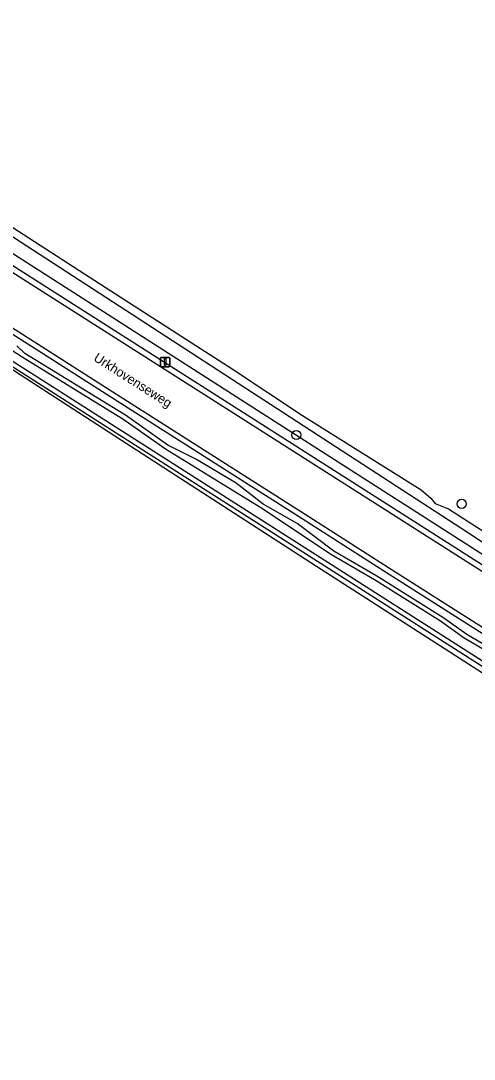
# Model space of a CAD drawing. Extents: x 164494 to 166241, y 382475 to 384494.
# Drawn here: x 165274.1 to 165322.7, y 382859.3 to 382970.6 of the extents above; entities that cross this region are included whole.
import ezdxf

# ---------------------------------------------------------------- set-up
doc = ezdxf.new("R2010")
doc.units = 0
for name, color, linetype in [('IMGEO_Berm_halfverhard', 7, 'Continuous'), ('IMGEO_Boom', 7, 'Continuous'), ('IMGEO_Grasland_agrarisch', 7, 'Continuous'), ('IMGEO_Groenvoorziening', 7, 'Continuous'), ('IMGEO_Hek', 7, 'Continuous'), ('IMGEO_Loofbos', 7, 'Continuous'), ('IMGEO_Openbare_ruimte_label', 7, 'Continuous'), ('IMGEO_Rijbaan_lokaal_gesloten', 7, 'Continuous'), ('IMGEO_Verkeersbordpaal', 7, 'Continuous'), ('IMGEO_Waterloop', 7, 'Continuous')]:
    doc.layers.add(name, color=color, linetype=linetype)

msp = doc.modelspace()

# ---------------------------------------------------------------- linework, layer by layer
at = {"layer": 'IMGEO_Berm_halfverhard'}
for points in [[(165252.94, 382956.51), (165253.27, 382957.02), (165336.85, 382903.81), (165336.73, 382903.62), (165352.54, 382893.38)], [(165351.59, 382887), (165346.66, 382890.15), (165339.82, 382894.53), (165330.45, 382900.53), (165322.57, 382905.52), (165313.17, 382911.49), (165304.23, 382917.2), (165295.7, 382922.63), (165290.59, 382925.86), (165282.82, 382930.8), (165276, 382935.15), (165269.08, 382939.56), (165261.99, 382944.04), (165250.07, 382951.57), (165250.4, 382952.08)]]:
    msp.add_lwpolyline(points, dxfattribs=at)
at = {"layer": 'IMGEO_Boom'}
for centre in [(165303.61, 382926.18), (165321.33, 382918.8)]:
    msp.add_circle(centre, 0.489, dxfattribs=at)
at = {"layer": 'IMGEO_Grasland_agrarisch'}
msp.add_lwpolyline([(165240.44, 382969.54), (165240.65, 382969.41), (165269.04, 382951.11), (165283.23, 382941.96), (165296.82, 382933.2), (165304.27, 382928.28), (165316.97, 382920.29), (165318.03, 382919.42), (165318.5, 382918.84), (165319.92, 382918.27), (165332.19, 382910.35), (165332.59, 382910.4), (165333.72, 382909.38), (165356.3, 382895.09), (165364.07, 382889.81), (165370.04, 382885.4), (165371.91, 382884.35), (165372.87, 382883.34)], dxfattribs=at)
at = {"layer": 'IMGEO_Groenvoorziening'}
msp.add_lwpolyline([(165363.51, 382875.32), (165364.7, 382877.15), (165360.69, 382879.91), (165359.12, 382880.68), (165347.27, 382888.35), (165336.18, 382895.87), (165332.89, 382897.74), (165327.6, 382901.45), (165321.86, 382904.8), (165319.31, 382906.62), (165312.22, 382911.06), (165307.64, 382913.72), (165303.7, 382916.7), (165300.05, 382918.77), (165297.15, 382921.02), (165292.89, 382923.56), (165289.84, 382925.08), (165285.28, 382928.29), (165284.46, 382928.79), (165274.52, 382934.91), (165273.65, 382935.73)], dxfattribs=at)
at = {"layer": 'IMGEO_Hek'}
for points in [[(165284.75, 382925.67), (165260.58, 382941.3), (165247.02, 382950.24)], [(165339.77, 382859.26), (165360.03, 382877.2), (165305.75, 382912.08), (165284.75, 382925.67)]]:
    msp.add_lwpolyline(points, dxfattribs=at)
at = {"layer": 'IMGEO_Loofbos'}
for points in [[(165339.77, 382859.26), (165360.03, 382877.2), (165305.75, 382912.08), (165284.75, 382925.67), (165260.58, 382941.3), (165247.02, 382950.24)], [(165247.02, 382950.24), (165260.73, 382941.64), (165271.58, 382934.54), (165284.7, 382926.17), (165326.65, 382899.4), (165363.51, 382875.32)]]:
    msp.add_lwpolyline(points, dxfattribs=at)
at = {"layer": 'IMGEO_Rijbaan_lokaal_gesloten'}
for points in [[(165252.94, 382956.51), (165336.52, 382903.3), (165343.27, 382899)], [(165250.4, 382952.08), (165262.31, 382944.54), (165269.4, 382940.07), (165276.32, 382935.66), (165283.14, 382931.31), (165290.91, 382926.37), (165296.02, 382923.13), (165304.55, 382917.7), (165313.49, 382911.99), (165322.89, 382906.02), (165330.77, 382901.04), (165340.15, 382895.04), (165346.98, 382890.66), (165351.91, 382887.51)]]:
    msp.add_lwpolyline(points, dxfattribs=at)
at = {"layer": 'IMGEO_Verkeersbordpaal'}
for p, q in [((165289.06, 382933.6), (165289.06, 382934.4)), ((165289.06, 382934.4), (165289.06, 382933.6)), ((165289.16, 382934.5), (165289.95, 382934.5)), ((165289.95, 382934.5), (165289.16, 382934.5)), ((165290.05, 382934.4), (165290.05, 382933.6)), ((165290.05, 382933.6), (165290.05, 382934.4)), ((165289.95, 382933.5), (165289.16, 382933.5)), ((165289.16, 382933.5), (165289.95, 382933.5))]:
    msp.add_line(p, q, dxfattribs=at)
msp.add_lwpolyline([(165289.48, 382934.38), (165289.63, 382934.38), (165289.63, 382933.63), (165289.48, 382933.63), (165289.48, 382934.38)], dxfattribs=at)
for centre, start, end in [((165289.16, 382934.4), 90, 180), ((165289.16, 382934.4), 90, 180), ((165289.95, 382934.4), 0, 90), ((165289.95, 382934.4), 360, 90), ((165289.16, 382933.6), 180, 270), ((165289.16, 382933.6), 180, 270), ((165289.95, 382933.6), 270, 0), ((165289.95, 382933.6), 270, 0)]:
    msp.add_arc(centre, 0.1, start, end, dxfattribs=at)
at = {"layer": 'IMGEO_Waterloop'}
for points in [[(165307.37, 382913.32), (165299.79, 382918.36), (165289.59, 382924.66), (165285.01, 382927.88), (165284.2, 382928.38), (165274.23, 382934.52), (165265.68, 382940.02), (165257.09, 382945.57), (165249.46, 382950.3), (165233.21, 382961.17), (165215.39, 382973.75), (165210.61, 382977.66), (165201.42, 382985.54), (165192.84, 382992.91), (165189.2, 382996.18), (165185.56, 382999.64), (165178.57, 383006.12), (165172.73, 383011.24), (165162.11, 383021.13), (165151.55, 383031.31)], [(165156.81, 383024.45), (165162.98, 383018.91), (165183.62, 383000.36), (165208.01, 382978.45), (165217.25, 382970.44), (165247.28, 382950.65), (165260.99, 382942.05), (165271.84, 382934.95), (165284.96, 382926.58), (165326.91, 382899.81), (165363.36, 382875.99), (165364.03, 382877.02), (165360.45, 382879.49), (165358.88, 382880.26), (165347, 382887.94), (165332.63, 382897.34), (165327.34, 382901.05), (165321.6, 382904.4), (165319.04, 382906.22), (165311.97, 382910.64), (165307.37, 382913.32)], [(165372.18, 382882.69), (165322.04, 382915.66), (165240.83, 382968.43), (165240.58, 382968.58), (165240.33, 382968.7), (165240.07, 382968.78), (165239.92, 382968.79), (165239.53, 382968.72), (165239.31, 382968.56), (165239.13, 382968.23), (165239.1, 382968.04), (165239.09, 382967.96), (165239.07, 382967.68)], [(165239.07, 382967.68), (165239.21, 382967.57), (165239.45, 382967.33), (165271.46, 382946.73), (165303.61, 382926.18), (165319.21, 382916.2), (165335.92, 382905.46), (165354.4, 382893.57), (165372.35, 382881.21)]]:
    msp.add_lwpolyline(points, dxfattribs=at)

# ---------------------------------------------------------------- texts
at = {"layer": 'IMGEO_Openbare_ruimte_label'}
msp.add_text('Urkhovenseweg', height=1, rotation=327.5024, dxfattribs=at).set_placement((165281.79, 382934.21))

doc.saveas('drawing.dxf')
